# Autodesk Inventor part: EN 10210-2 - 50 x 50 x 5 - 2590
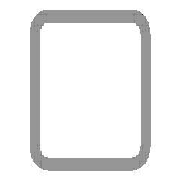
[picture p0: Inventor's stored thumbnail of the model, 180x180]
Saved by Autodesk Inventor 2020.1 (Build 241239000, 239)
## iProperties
_CCFamilyMember: 16
_CCFamilyDisplayName: DIN EN 10210-2 (USAS B17.1 quadratisch) - Rohrleitung — In Klammern angegebene Größen wurden aufgehoben
_FrameMemberDoc: Frame Member File
_Version: 15.0.0
_GetPNFromCC: 1
IsCustomPart: 1
Created: 2019-10
Part Number: EN 10210-2 - 50 x 50 x 5 - 2590
Material: Stahl, weich
Description: Rohrleitung
Document SubType Name: Modeling
Standard: DIN
Designer: lutzd
Standard Revision: 2006-07
Standards Organization: DIN
Language: de-DE
Size Designation: 50 x 50 x 5
Categories: <MemberInstance><Categories><Category DisplayName="Profile" InternalName="089c4875-fa83-4c05-b084-43b9cc11f5ed" Mnemonic="GRDR"><CategoryParameter DisplayName="
Stock Number: 50 x 50 x 5
Mass: 17753 g
Surface Area: 8785.64 cm^2
Volume: 2261.52 cm^3
Density: 7.85 g/cm^3
Appearance: Halbpoliert
G_L: 2590,000 mm
G_W: 50,000 mm
G_H: 50,000 mm
Dimensions: 50x50x2590 mm
Mass: 17,753 kg
DocNumber: ADSK-014094
Folder: .
+6FE753BB-AAB6-4FAC-8710-18412902704B+SCHNITTDETAIL1: Schnittwinkel 90,00 grd
+81D69739-CB75-4929-B183-A4E252010A32+SCHNITTDETAIL2: Schnittwinkel 90,00 grd
Title: Profil-Bauteil
Author: lutzd
Revision Number: -
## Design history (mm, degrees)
node "Startebene"
node "Endebene"
sketch "Skizze"
  geometry: L1 (-25, -17.5)-(-25, 17.5); L2 (-17.5, 25)-(17.5, 25); L3 (25, 17.5)-(25, -17.5); L4 (17.5, -25)-(-17.5, -25); L5 (-15, 20)-(15, 20); L6 (20, 15)-(20, -15); L7 (15, -20)-(-15, -20); L8 (-20, -15)-(-20, 15); L9 (0, 37.175)-(0, -37.175) reference; L10 (-37.175, 0)-(37.175, 0) reference; A1 r 7.5 centre (-17.5, -17.5) between (-25, -17.5) and (-17.5, -25); A2 r 7.5 centre (-17.5, 17.5) between (-17.5, 25) and (-25, 17.5); A3 r 7.5 centre (17.5, 17.5) between (25, 17.5) and (17.5, 25); A4 r 7.5 centre (17.5, -17.5) between (17.5, -25) and (25, -17.5); A5 r 5 centre (-15, -15) between (-20, -15) and (-15, -20); A6 r 5 centre (-15, 15) between (-15, 20) and (-20, 15); A7 r 5 centre (15, 15) between (20, 15) and (15, 20); A8 r 5 centre (15, -15) between (15, -20) and (20, -15)
  constraints: 16 end point, 16 point on circle, 16 tangent, 8 centre point, 6 equal radius, 4 parallel, 2 perpendicular, 2 other
  dimensions: "d7" = 7.5 radius of A1 (= G_IR); "d10" = 50 distance between parallel lines of L2 L4 (= G_H); "d11" = 50 distance between parallel lines of L1 L3 (= G_W); "d12" = 5 distance between parallel lines of L3 L6 (= G_T); "d15" = 25 distance between parallel lines of L2 L10 (= 0.5 x d10); "d16" = 25 distance between parallel lines of L9 L3 (= 0.5 x d11); "d19" = 5 radius of A5 (= G_T); "d20" = 5 distance between parallel lines of L4 L7 (= G_T)
extrude "Körper" new body sketch "Skizze" stored distance "d3" = 2590 (= G_L); taper "d4" = 0 deg
node "Driven Length"
  sketch "Sketch3"
    geometry: L1 (0, 0)-(10, 0) reference
    constraints: 2 end point, 1 horizontal
  workplane "Work Plane3"
  sketch "Sketch4"
    geometry: L1 (-2, 50)-(12, 50) reference; L2 (-2, 2640)-(12, 2640) reference
    dimensions: "d18" = 2590 distance between parallel lines of L1 L2 (derived)
workplane "Arbeitsebene4"
feature "Trennen1"
workplane "Arbeitsebene5"
feature "Trennen2"
body "Solid1"
other parameters: "G_W" = 50 [user parameter; used in 1 equation term], "G_H" = 50 [user parameter; used in 1 equation term], "G_T" = 5 [user parameter; used in 3 equation terms], "G_IR" = 7.5 [user parameter; used in 1 equation term], "G_L" = 2590 (= d18) [user parameter; used in 1 equation term], "d17" = 90 deg
